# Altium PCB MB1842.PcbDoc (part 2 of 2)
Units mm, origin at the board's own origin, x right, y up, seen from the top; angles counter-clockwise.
Board outline 64.57 x 35 mm, 4 copper layers (Top Layer, MidLayer 1, MidLayer 2, Bottom Layer), stack 1.066 mm thick; 81 components, 72 nets, 272 pads, 1151 vias.
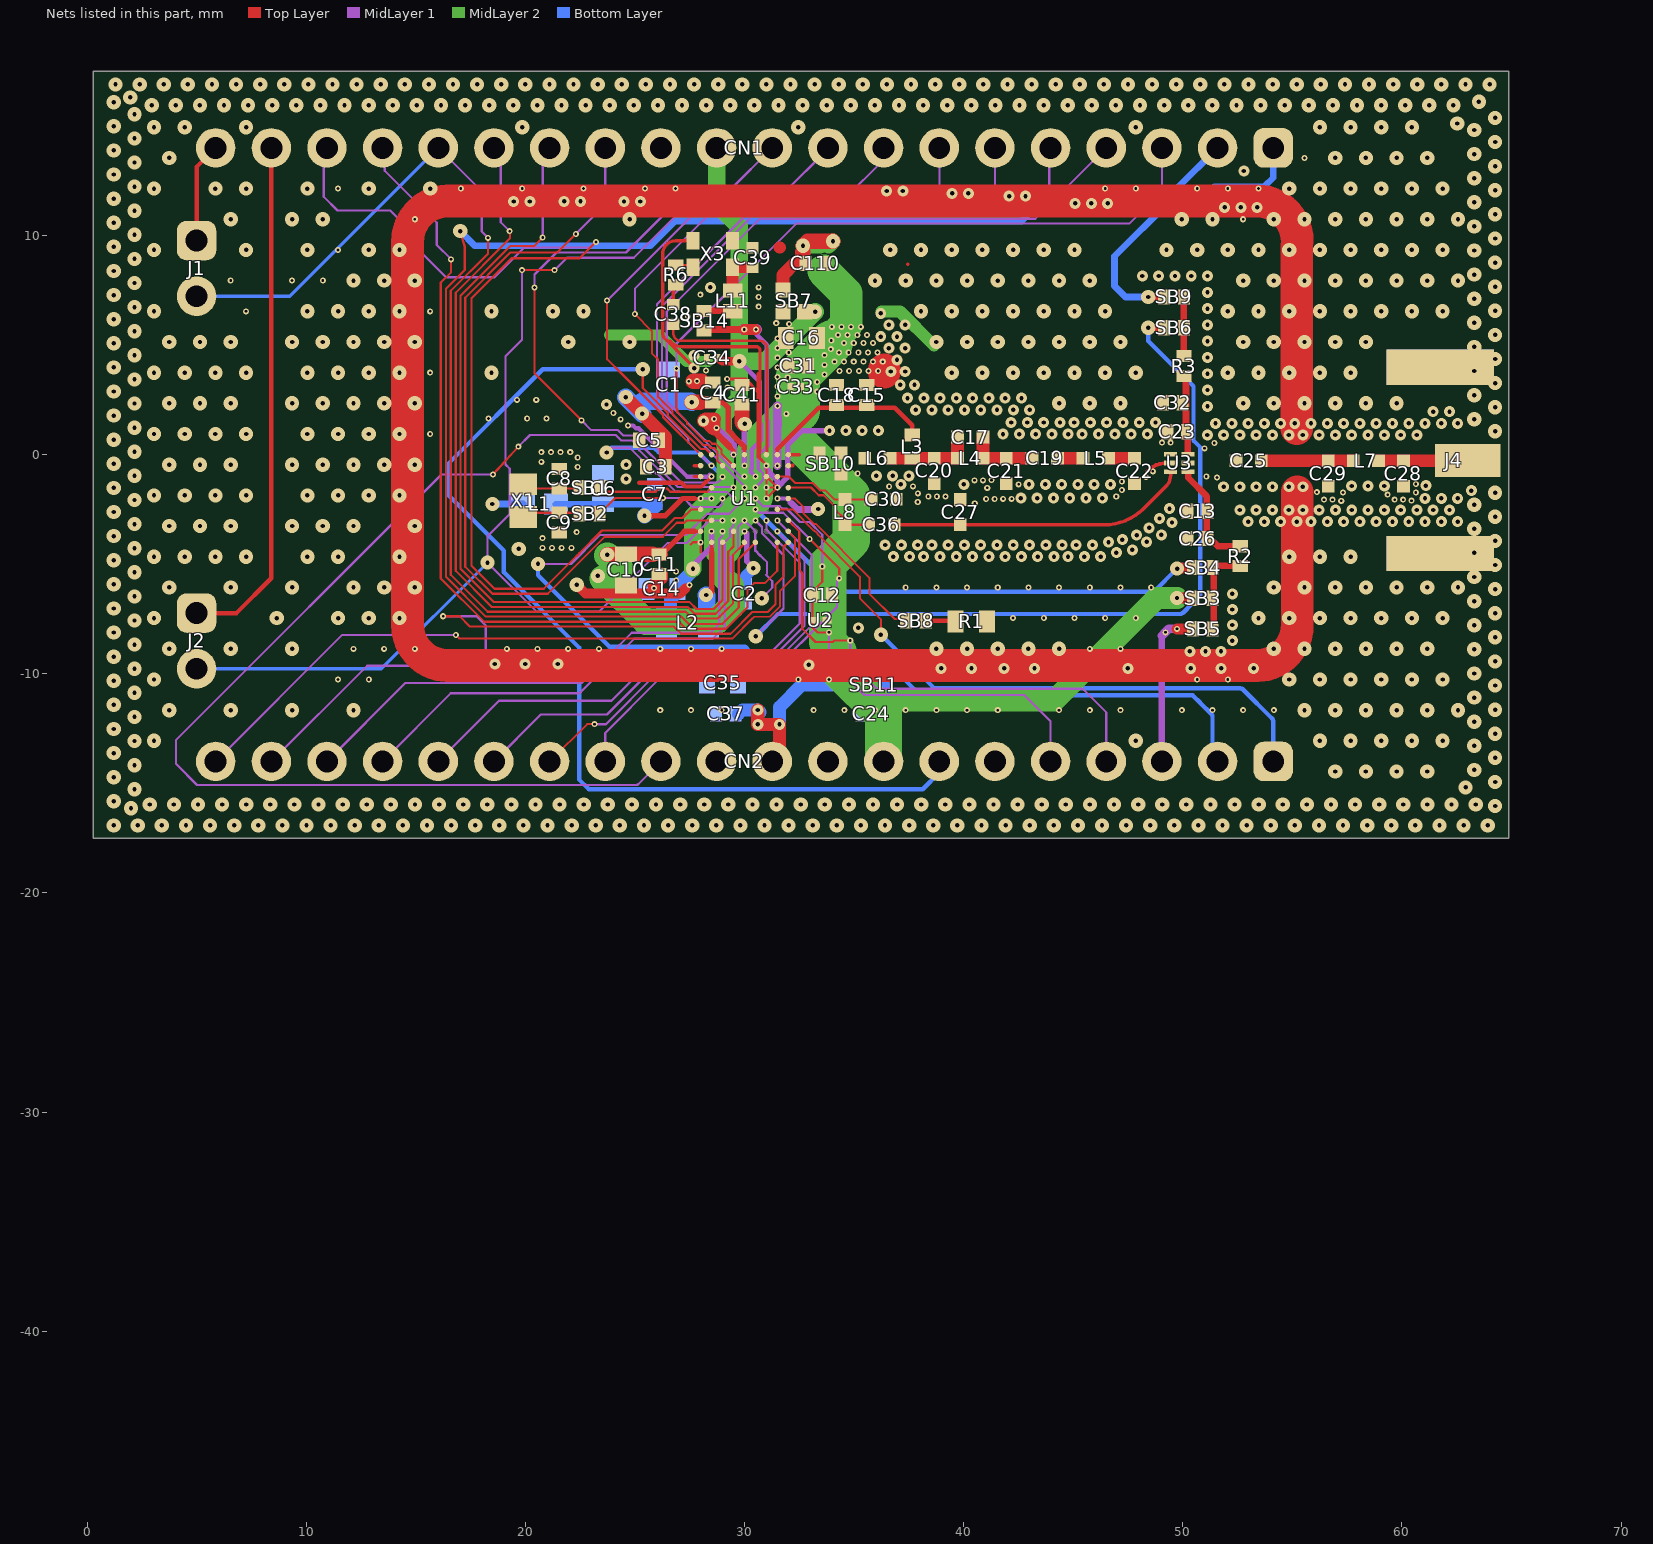
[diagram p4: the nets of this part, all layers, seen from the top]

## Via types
v1: diameter 0.65, hole 0.2, Top Layer to Bottom Layer, 646 vias
v2: diameter 0.275, hole 0.125, Top Layer to MidLayer 1, 261 vias
v3: diameter 0.5, hole 0.2, Top Layer to Bottom Layer, 244 vias

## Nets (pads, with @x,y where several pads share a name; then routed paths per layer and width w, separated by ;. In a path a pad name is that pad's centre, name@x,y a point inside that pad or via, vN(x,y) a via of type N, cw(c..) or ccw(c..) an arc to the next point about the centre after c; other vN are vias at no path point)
GND: C1.1 C2.1 C3.1 C4.1 C5.1 C6.2 C7.2 C8.2 C9.2 C10.2 C11.2 C12.2 C13.1 C14.2 C15.1 C16.2 C18.2 C20.2 C21.1 C22.1 C23.1 C24.2 C26.2 C27.1 C28.2 C29.2 C30.1 C31.2 C32.2 C33.1 C34.1 C35.2 C37.2 C39.1 C41.2 C110.2 CN1.12 CN2.6 CN2.9 CN2.11 J4.2 R1.1 U1.A1 U1.B7 U1.D9 U1.E3 U1.G5 U1.G6 U1.G7 U1.G8 U1.H6 U2.2 U3.2 X3.1 X3.2 | length 185.7
  Top Layer w0.1: 27.55,-4.1 27.65,-4 v2(28,-4) 28,-4.45 ; 28.26,-1.23 28.277,-1.23 ; 30.822,-0.285 31,-0.463 v2(31,-0.5) U1.G7@31,-1 ; U1.G7@31.008,-1 U1.G7@31,-1 ; v2(31,-1.5) v2(31,-2) v2(31.5,-1.5) ; v2(31,-1.5) v2(31.5,-1.5) ; v2(31,-1.5) U1.G7@31,-1 ; U1.G7@31,-1 v2(31.5,-1.5)
  Top Layer w0.15: 27.129,4.929 cw(c27.129,5.562) 26.626,5.177 ; v3@27.614,4.053 26.49,5.177 ; X3.2@27.649,9.76 26.867,9.76 ccw(c26.867,9.159) 26.533,9.658 ccw(c26.867,9.159) 26.368,9.493 ccw(c26.867,9.159) 26.266,9.159 26.266,5.536 ccw(c26.626,5.536) 26.321,5.346 26.435,5.232 ; 28.277,-1.23 28.5,-1.008 v2(28.5,-1) ; v2(29.214,3.454) 30.034,3.454 30.634,2.854 ; 30.529,4.929 cw(c30.529,4.748) 30.71,4.748 30.71,0.135 ccw(c31,0) 30.689,-0.075 cw(c30.634,-0.022) 30.634,-0.098 ; 30.634,3.698 30.634,2.854 ; 30.822,-0.285 30.634,-0.098 ; 37.446,8.695 37.448,8.697 ; 26.435,5.232 ccw(c26.626,5.536) 26.626,5.177 ; 26.435,5.232 26.49,5.177 ; 26.49,5.177 26.626,5.177 ; 30.634,-0.098 30.634,2.854
  Top Layer w0.16: 27.129,4.924 30.529,4.924 30.529,4.929
  Top Layer w0.17: 29.338,0.347 29.5,0.185 v2(29.5,0)
  Top Layer w0.18: 48.368,-0.759 cw(c49.284,-1.674) 49.284,-0.38 U3.2@49.448,-0.38
  Top Layer w0.2: 25.208,-1.275 27.12,-1.275 27.3,-1.455 28.035,-1.455 28.26,-1.23
  Top Layer w0.3: 28.753,0.932 29.338,0.347
  Top Layer w0.45: v1(22.349,-5.934) 22.749,-6.334 25.113,-6.334 27.072,-6.334 27.312,-6.094
  Top Layer w0.55: 31.606,9.448 31.613,9.454
  Top Layer w0.6: v2@25.865,-5.967 26.204,-5.628 C11.2@26.204,-5.452 ; v3@28.175,1.53 28.145,1.53 v3(28.132,1.544) 28.217,1.629 v2(28.621,1.629) 28.604,1.613 28.604,1.169 v3@28.212,1.561
  Top Layer w0.7: 27.67,3.355 27.708,3.355 v2(27.839,3.355) 28.058,3.355
  Top Layer w1.5: 36.377,3.769 36.377,3.865 ; 55.203,1.185 55.203,9.519 ; 55.225,-7.823 55.225,-1.707 ; 55.228,-7.775 cw(c53.378,-7.775) 53.378,-9.625 16.478,-9.625 cw(c16.478,-7.775) 14.628,-7.775 14.628,9.725 cw(c16.478,9.725) 16.478,11.575 53.378,11.575 cw(c53.378,9.725) 55.228,9.725
  MidLayer 1 w0.1: 29.5,-5.45 29.375,-5.325 29.375,-4.675 29.708,-4.342 29.708,-3.292 v2(30,-3) 30.442,-3.442 ; 30.718,-4.6 30.85,-4.733 31.034,-4.916 31.034,-5.434 30.982,-5.486 31.272,-5.776 31.272,-6.066 v1(30.788,-6.55)
  MidLayer 1 w0.12: 30.442,-3.442 30.5,-3.5 30.5,-4.382 30.718,-4.6
  MidLayer 1 w0.2: v2(24.691,1.329) 24.918,1.329 25.049,1.199 25.179,1.199 27.378,-1 v2(28.5,-1) v2@28.415,-0.915
  MidLayer 1 w0.25: v2(31,-0.5) 31,-0.631 31.109,-0.74 31.109,-0.796 31.5,-1.187 v2(31.5,-1.5) 31.974,-1.026 31.974,0.436 32.635,1.096 v3(33.881,1.096)
  MidLayer 1 w0.3: v2(28.73,1.223) 29.5,0.452 v2(29.5,0)
  MidLayer 2 w0.5: 23.838,5.458 26.144,5.458 27.358,4.244 28.362,4.244
  MidLayer 2 w0.55: v3@36.252,6.537 37.096,6.537 v1@38.64,4.993
  other v1: 1.215,-16.917 2.315,-16.917 3.415,-16.917 4.515,-16.917 5.615,-16.917 6.715,-16.917 7.815,-16.917 8.915,-16.917 10.015,-16.917 11.115,-16.917 12.215,-16.917 13.315,-16.917 14.415,-16.917 15.515,-16.917 16.615,-16.917 17.715,-16.917 18.815,-16.917 19.915,-16.917 21.015,-16.917 22.115,-16.917 23.215,-16.917 24.315,-16.917 25.415,-16.917 26.515,-16.917 27.615,-16.917 28.715,-16.917 29.815,-16.917 30.915,-16.917 32.015,-16.917 33.115,-16.917 34.215,-16.917 35.315,-16.917 36.415,-16.917 37.515,-16.917 38.615,-16.917 39.715,-16.917 40.815,-16.917 41.915,-16.917 43.015,-16.917 44.115,-16.917 45.215,-16.917 46.315,-16.917 47.415,-16.917 48.515,-16.917 49.615,-16.917 50.715,-16.917 51.815,-16.917 52.915,-16.917 54.015,-16.917 55.115,-16.917 56.215,-16.917 57.315,-16.917 58.415,-16.917 59.515,-16.917 60.615,-16.917 61.715,-16.917 62.815,-16.917 63.915,-16.917 2.005,-16.137 64.253,-16.034 2.865,-15.964 3.965,-15.964 5.065,-15.964 6.165,-15.964 7.265,-15.964 8.365,-15.964 9.465,-15.964 10.565,-15.964 11.665,-15.964 12.765,-15.964 13.865,-15.964 14.965,-15.964 16.065,-15.964 17.165,-15.964 18.265,-15.964 19.365,-15.964 20.465,-15.964 21.565,-15.964 22.665,-15.964 23.765,-15.964 24.865,-15.964 25.965,-15.964 27.065,-15.964 28.165,-15.964 29.265,-15.964 30.365,-15.964 31.465,-15.964 32.565,-15.964 33.665,-15.964 34.765,-15.964 35.865,-15.964 36.965,-15.964 38.065,-15.964 39.165,-15.964 40.265,-15.964 41.365,-15.964 42.465,-15.964 43.565,-15.964 44.665,-15.964 45.765,-15.964 46.865,-15.964 47.965,-15.964 49.065,-15.964 50.165,-15.964 51.265,-15.964 52.365,-15.964 53.465,-15.964 54.565,-15.964 55.665,-15.964 56.765,-15.964 57.865,-15.964 58.965,-15.964 60.065,-15.964 61.165,-15.964 62.265,-15.964 63.365,-15.964 1.215,-15.817 2.168,-15.267 62.908,-15.185 64.253,-14.934 1.215,-14.717 56.958,-14.458 58.358,-14.458 59.758,-14.458 61.158,-14.458 63.3,-14.384 2.168,-14.167 64.253,-13.834 1.215,-13.617 63.3,-13.284 2.168,-13.067 3.058,-13.058 47.858,-13.058 56.258,-13.058 57.658,-13.058 59.058,-13.058 60.458,-13.058 61.858,-13.058 64.253,-12.734 1.215,-12.517 63.3,-12.184 2.168,-11.967 3.758,-11.658 6.558,-11.658 9.358,-11.658 12.158,-11.658 55.558,-11.658 56.958,-11.658 58.358,-11.658 59.758,-11.658 61.158,-11.658 62.558,-11.658 64.253,-11.634 1.215,-11.417 63.3,-11.084 2.168,-10.867 64.253,-10.534 1.215,-10.317 3.058,-10.258 54.858,-10.258 56.258,-10.258 57.658,-10.258 59.058,-10.258 60.458,-10.258 61.858,-10.258 63.3,-9.984 2.168,-9.767 64.253,-9.434 1.215,-9.217 63.3,-8.884 3.758,-8.858 6.558,-8.858 9.358,-8.858 38.758,-8.858 40.158,-8.858 41.558,-8.858 42.958,-8.858 44.358,-8.858 54.158,-8.858 55.558,-8.858 56.958,-8.858 58.358,-8.858 59.758,-8.858 61.158,-8.858 2.168,-8.667 64.253,-8.334 1.215,-8.117 63.3,-7.784 2.168,-7.567 3.058,-7.458 8.658,-7.458 11.458,-7.458 12.858,-7.458 14.258,-7.458 53.458,-7.458 54.858,-7.458 56.258,-7.458 57.658,-7.458 59.058,-7.458 60.458,-7.458 61.858,-7.458 64.253,-7.234 1.215,-7.017 63.3,-6.684 2.168,-6.467 64.253,-6.134 3.758,-6.058 6.558,-6.058 9.358,-6.058 12.158,-6.058 13.558,-6.058 14.958,-6.058 54.158,-6.058 55.558,-6.058 56.958,-6.058 58.358,-6.058 59.758,-6.058 61.158,-6.058 62.558,-6.058 1.215,-5.917 63.3,-5.584 2.168,-5.367 64.253,-5.034 1.215,-4.817 3.058,-4.658 4.458,-4.658 5.858,-4.658 7.258,-4.658 10.058,-4.658 11.458,-4.658 14.258,-4.658 54.858,-4.658 56.258,-4.658 57.658,-4.658 63.3,-4.484 19.7,-4.3 2.168,-4.267 64.253,-3.934 1.215,-3.717 63.3,-3.384 3.758,-3.258 5.158,-3.258 6.558,-3.258 9.358,-3.258 10.758,-3.258 12.158,-3.258 14.958,-3.258 2.168,-3.167 64.253,-2.834 1.215,-2.617 63.3,-2.284 2.168,-2.067 3.058,-1.858 4.458,-1.858 5.858,-1.858 7.258,-1.858 10.058,-1.858 11.458,-1.858 12.858,-1.858 14.258,-1.858 64.253,-1.734 1.215,-1.517 2.168,-0.967 3.758,-0.458 5.158,-0.458 6.558,-0.458 9.358,-0.458 10.758,-0.458 12.158,-0.458 13.558,-0.458 14.958,-0.458 1.215,-0.417 2.168,0.133 1.215,0.683 3.058,0.942 4.458,0.942 5.858,0.942 7.258,0.942 10.058,0.942 11.458,0.942 12.858,0.942 14.258,0.942 64.253,1.066 2.168,1.233 63.3,1.616 1.215,1.783 64.253,2.166 2.168,2.333 3.758,2.342 5.158,2.342 6.558,2.342 9.358,2.342 10.758,2.342 12.158,2.342 13.558,2.342 14.958,2.342 44.358,2.342 45.758,2.342 47.158,2.342 52.758,2.342 54.158,2.342 55.558,2.342 56.958,2.342 58.358,2.342 59.758,2.342 63.3,2.716 1.215,2.883 64.253,3.266 2.168,3.433 3.058,3.742 4.458,3.742 5.858,3.742 7.258,3.742 10.058,3.742 11.458,3.742 12.858,3.742 14.258,3.742 18.458,3.742 39.458,3.742 40.858,3.742 42.258,3.742 43.658,3.742 45.058,3.742 46.458,3.742 47.858,3.742 52.058,3.742 53.458,3.742 54.858,3.742 56.258,3.742 57.658,3.742 63.3,3.816 1.215,3.983 64.253,4.366 2.168,4.533 63.3,4.916 1.215,5.083 3.758,5.142 5.158,5.142 6.558,5.142 9.358,5.142 10.758,5.142 12.158,5.142 13.558,5.142 14.958,5.142 21.958,5.142 24.758,5.142 38.758,5.142 40.158,5.142 41.558,5.142 42.958,5.142 44.358,5.142 45.758,5.142 47.158,5.142 52.758,5.142 54.158,5.142 55.558,5.142 56.958,5.142 58.358,5.142 64.253,5.466 2.168,5.633 63.3,6.016 1.215,6.183 3.058,6.542 10.058,6.542 11.458,6.542 12.858,6.542 14.258,6.542 18.458,6.542 21.258,6.542 22.658,6.542 38.058,6.542 39.458,6.542 40.858,6.542 42.258,6.542 43.658,6.542 45.058,6.542 46.458,6.542 52.058,6.542 53.458,6.542 54.858,6.542 56.258,6.542 57.658,6.542 59.058,6.542 60.458,6.542 61.858,6.542 64.253,6.566 2.168,6.733 63.3,7.116 1.215,7.283 64.253,7.666 2.168,7.833 12.158,7.942 13.558,7.942 14.958,7.942 35.958,7.942 37.358,7.942 38.758,7.942 40.158,7.942 41.558,7.942 42.958,7.942 44.358,7.942 45.758,7.942 52.758,7.942 54.158,7.942 55.558,7.942 56.958,7.942 58.358,7.942 59.758,7.942 61.158,7.942 62.558,7.942 63.3,8.216 1.215,8.383 64.253,8.766 2.168,8.933 63.3,9.316 3.058,9.342 7.258,9.342 10.058,9.342 12.858,9.342 14.258,9.342 36.658,9.342 38.058,9.342 39.458,9.342 40.858,9.342 42.258,9.342 43.658,9.342 45.058,9.342 49.258,9.342 50.658,9.342 52.058,9.342 53.458,9.342 54.858,9.342 56.258,9.342 57.658,9.342 59.058,9.342 60.458,9.342 61.858,9.342 1.215,9.483 64.253,9.866 2.168,10.033 63.3,10.416 1.215,10.583 6.558,10.742 9.358,10.742 10.758,10.742 24.758,10.742 49.958,10.742 51.358,10.742 54.158,10.742 55.558,10.742 56.958,10.742 58.358,10.742 59.758,10.742 61.158,10.742 62.558,10.742 64.253,10.966 2.168,11.133 63.3,11.516 1.215,11.683 64.253,12.066 3.058,12.142 5.858,12.142 7.258,12.142 10.058,12.142 12.858,12.142 15.658,12.142 54.858,12.142 56.258,12.142 57.658,12.142 59.058,12.142 60.458,12.142 61.858,12.142 2.168,12.233 63.3,12.616 1.215,12.783 64.253,13.166 2.168,13.333 3.758,13.542 56.958,13.542 58.358,13.542 59.758,13.542 61.158,13.542 63.3,13.716 1.215,13.883 64.253,14.266 2.168,14.433 63.3,14.816 3.058,14.942 4.458,14.942 7.258,14.942 19.858,14.942 32.458,14.942 47.858,14.942 56.258,14.942 57.658,14.942 59.058,14.942 60.458,14.942 1.215,14.983 62.526,15.112 64.253,15.366 2.168,15.533 2.952,15.942 4.052,15.942 5.152,15.942 6.252,15.942 7.352,15.942 8.452,15.942 9.552,15.942 10.652,15.942 11.752,15.942 12.852,15.942 13.952,15.942 15.052,15.942 16.152,15.942 17.252,15.942 18.352,15.942 19.452,15.942 20.552,15.942 21.652,15.942 22.752,15.942 23.852,15.942 24.952,15.942 26.052,15.942 27.152,15.942 28.252,15.942 29.352,15.942 30.452,15.942 31.552,15.942 32.652,15.942 33.752,15.942 34.852,15.942 35.952,15.942 37.052,15.942 38.152,15.942 39.252,15.942 40.352,15.942 41.452,15.942 42.552,15.942 43.652,15.942 44.752,15.942 45.852,15.942 46.952,15.942 48.052,15.942 49.152,15.942 50.252,15.942 51.352,15.942 52.452,15.942 53.552,15.942 54.652,15.942 55.752,15.942 56.852,15.942 57.952,15.942 59.052,15.942 60.152,15.942 61.252,15.942 62.352,15.942 1.215,16.083 63.513,16.099 1.97,16.301 1.302,16.895 2.402,16.895 3.502,16.895 4.602,16.895 5.702,16.895 6.802,16.895 7.902,16.895 9.002,16.895 10.102,16.895 11.202,16.895 12.302,16.895 13.402,16.895 14.502,16.895 15.602,16.895 16.702,16.895 17.802,16.895 18.902,16.895 20.002,16.895 21.102,16.895 22.202,16.895 23.302,16.895 24.402,16.895 25.502,16.895 26.602,16.895 27.702,16.895 28.802,16.895 29.902,16.895 31.002,16.895 32.102,16.895 33.202,16.895 34.302,16.895 35.402,16.895 36.502,16.895 37.602,16.895 38.702,16.895 39.802,16.895 40.902,16.895 42.002,16.895 43.102,16.895 44.202,16.895 45.302,16.895 46.402,16.895 47.502,16.895 48.602,16.895 49.702,16.895 50.802,16.895 51.902,16.895 53.002,16.895 54.102,16.895 55.202,16.895 56.302,16.895 57.402,16.895 58.502,16.895 59.602,16.895 60.702,16.895 61.802,16.895 62.902,16.895 64.002,16.895
  other v2: 26.158,-11.658 27.558,-11.658 28.958,-11.658 33.158,-11.658 34.558,-11.658 35.958,-11.658 37.358,-11.658 38.758,-11.658 40.158,-11.658 41.558,-11.658 44.358,-11.658 45.758,-11.658 47.158,-11.658 49.958,-11.658 51.358,-11.658 52.758,-11.658 54.158,-11.658 11.458,-10.258 12.858,-10.258 32.458,-10.258 33.858,-10.258 50.658,-10.258 52.058,-10.258 12.158,-8.858 13.558,-8.858 14.958,-8.858 19.158,-8.858 20.558,-8.858 21.958,-8.858 23.358,-8.858 26.158,-8.858 27.558,-8.858 28.958,-8.858 45.758,-8.858 47.158,-8.858 42.258,-7.458 43.658,-7.458 45.058,-7.458 46.458,-7.458 47.858,-7.458 25.868,-6.09 37.358,-6.058 38.758,-6.058 40.158,-6.058 41.558,-6.058 42.958,-6.058 44.358,-6.058 45.758,-6.058 47.158,-6.058 48.558,-6.058 27.495,-5.952 26.885,-5.738 26.885,-5.33 20.78,-4.252 21.221,-4.252 21.662,-4.252 22.103,-4.252 20.78,-3.811 22.343,-3.539 40.509,-2.219 37.908,-2.157 57.233,-2.109 60.44,-2.101 56.449,-2.054 56.838,-2.056 59.669,-2.053 60.058,-2.055 41.029,-2.019 41.418,-2.018 41.807,-2.016 42.196,-2.015 38.391,-1.909 38.78,-1.911 39.169,-1.912 46.965,-1.913 59.352,-1.829 37.91,-1.765 56.119,-1.713 57.314,-1.729 60.634,-1.728 47.218,-1.615 41.08,-1.511 36.606,-1.454 37.686,-1.444 42.514,-1.351 60.636,-1.339 47.22,-1.223 40.497,-1.17 40.886,-1.168 41.275,-1.167 51.56,-1.047 48.334,-1.012 51.077,-0.998 35.167,-0.859 48.635,-0.762 22.388,-0.568 20.728,-0.326 22.388,-0.127 20.728,0.115 21.169,0.115 21.61,0.115 22.051,0.115 50.998,0.289 49.05,0.549 49.449,0.549 51.441,0.533 15.658,0.942 24.353,1.613 18.322,1.648 20.086,1.648 20.967,1.648 24.015,1.896 19.617,2.501 20.499,2.501 33.317,2.874 29.224,3.075 33.317,3.315 27.459,3.346 33.655,3.66 15.658,3.742 34.34,3.814 34.781,3.814 35.222,3.814 35.663,3.814 36.103,3.814 28.244,3.84 33.655,4.101 34.106,4.241 34.547,4.241 34.988,4.241 35.429,4.241 35.869,4.241 36.31,4.241 33.655,4.542 34.313,4.667 34.754,4.667 35.194,4.667 35.635,4.667 36.076,4.667 33.942,4.813 34.547,5.093 34.988,5.093 35.428,5.093 35.869,5.093 33.966,5.21 34.266,5.464 34.707,5.464 35.148,5.464 35.589,5.464 33.986,5.835 34.426,5.835 34.867,5.835 35.308,5.835 27.418,6.313 7.258,6.542 15.658,6.542 30.649,6.755 30.649,7.196 27.987,7.3 30.649,7.637 6.558,7.942 9.358,7.942 10.758,7.942 11.458,9.342 14.958,10.742 52.758,10.742 11.458,12.142 17.058,12.142 19.858,12.142 22.658,12.142 25.458,12.142 26.858,12.142 46.458,12.142 47.858,12.142 50.658,12.142 52.058,12.142 53.458,12.142 55.558,13.542
  other v3: 38.976,-9.752 40.363,-9.752 41.849,-9.752 43.235,-9.752 47.494,-9.752 50.366,-9.752 51.753,-9.752 53.239,-9.752 32.938,-9.592 18.609,-9.554 19.996,-9.554 21.482,-9.554 50.327,-8.977 51.037,-8.977 51.747,-8.977 52.265,-8.484 35.2,-7.9 52.265,-7.774 52.265,-7.064 52.265,-6.354 36.792,-4.654 37.535,-4.654 38.178,-4.654 38.922,-4.654 39.665,-4.654 40.408,-4.654 41.151,-4.654 41.894,-4.654 42.637,-4.654 43.38,-4.654 44.123,-4.654 44.767,-4.654 45.51,-4.654 46.253,-4.654 46.973,-4.469 47.705,-4.34 36.42,-4.122 37.163,-4.122 37.907,-4.122 38.55,-4.122 39.293,-4.122 40.036,-4.122 40.779,-4.122 41.522,-4.122 42.265,-4.122 43.008,-4.122 43.752,-4.122 44.495,-4.122 45.138,-4.122 45.881,-4.122 46.613,-3.993 48.352,-3.976 47.246,-3.882 47.896,-3.671 49.026,-3.662 48.464,-3.337 49.51,-3.098 52.982,-3.058 53.725,-3.058 54.468,-3.058 55.211,-3.058 55.854,-3.058 56.597,-3.058 57.34,-3.058 58.083,-3.058 58.827,-3.058 59.57,-3.058 60.313,-3.058 61.056,-3.058 61.799,-3.058 62.542,-3.058 48.942,-2.914 52.61,-2.527 53.353,-2.527 54.096,-2.527 54.839,-2.527 55.482,-2.527 56.225,-2.527 56.968,-2.527 57.712,-2.527 58.455,-2.527 59.198,-2.527 59.941,-2.527 60.684,-2.527 61.427,-2.527 62.17,-2.527 49.397,-2.46 42.614,-1.988 43.357,-1.988 44.1,-1.988 44.844,-1.988 45.587,-1.988 46.33,-1.988 61.055,-1.995 61.798,-1.995 62.541,-1.995 63.17,-1.64 51.866,-1.464 52.609,-1.464 53.352,-1.464 54.095,-1.464 54.838,-1.464 55.481,-1.464 57.71,-1.429 58.453,-1.429 59.197,-1.429 61.09,-1.411 37.14,-1.356 40.013,-1.356 42.985,-1.356 43.729,-1.356 44.472,-1.356 45.215,-1.356 45.958,-1.356 46.701,-1.356 24.598,-1.104 36.019,-0.967 36.762,-0.967 37.505,-0.967 24.598,-0.458 51.123,0.898 51.866,0.898 52.609,0.898 53.352,0.898 54.095,0.898 54.838,0.898 55.481,0.898 56.225,0.898 56.968,0.898 57.711,0.898 58.454,0.898 59.197,0.898 59.94,0.898 60.683,0.898 41.798,0.938 42.541,0.938 43.284,0.938 44.027,0.938 44.77,0.938 45.413,0.938 46.156,0.938 46.899,0.938 47.643,0.938 48.386,0.938 34.624,1.096 35.367,1.096 36.11,1.096 51.495,1.43 52.238,1.43 52.981,1.43 53.724,1.43 54.467,1.43 55.11,1.43 55.853,1.43 56.596,1.43 57.34,1.43 58.083,1.43 58.826,1.43 59.569,1.43 60.312,1.43 61.055,1.43 61.798,1.43 62.541,1.43 42.169,1.469 42.913,1.469 43.656,1.469 44.399,1.469 45.042,1.469 45.785,1.469 46.528,1.469 47.271,1.469 48.014,1.469 48.758,1.469 61.427,1.961 62.17,1.961 37.812,2.046 38.555,2.046 39.297,2.046 40.04,2.046 40.784,2.046 41.527,2.046 42.27,2.046 43.013,2.046 51.132,2.205 23.706,2.287 37.441,2.577 38.184,2.577 38.927,2.577 39.669,2.577 40.412,2.577 41.155,2.577 41.898,2.577 42.641,2.577 51.132,2.948 37.109,3.185 37.758,3.186 51.132,3.692 36.683,3.794 37.332,3.794 27.708,3.949 36.961,4.326 51.132,4.435 27.708,4.532 36.59,4.857 37.333,4.857 51.132,5.178 36.219,5.389 36.962,5.389 36.591,5.92 37.334,5.92 51.132,5.921 36.219,6.452 51.132,6.664 51.132,7.407 28.441,7.636 48.16,8.15 48.903,8.15 49.646,8.15 50.389,8.15 51.132,8.15 51.912,11.286 52.655,11.286 53.399,11.286 45.088,11.465 45.832,11.465 46.575,11.465 19.467,11.55 20.21,11.55 24.503,11.554 25.246,11.554 21.776,11.558 22.519,11.558 42.082,11.793 42.825,11.793 39.477,11.926 40.22,11.926 36.488,12.029 37.231,12.029 52.785,12.942
NetC6_1: C6.1 C7.1 L1.2 U1.A5 U1.B5 | length 8.2
  Top Layer w0.15: 27.7,-2 v2(28,-2)
  Top Layer w0.25: v1@25.623,-2.796 26.378,-2.796 27.174,-2 27.7,-2
  MidLayer 1 w0.1: v2(28,-2) v2(28.5,-2)
  Bottom Layer w0.25: C6.1@23.45,-2.462 C6.1@23.462,-2.45
  Bottom Layer w0.3: L1.2@21.4,-2.262 C6.1@23.55,-2.262 ; C6.1@23.678,-2.266 23.688,-2.256 C7.1@25.89,-2.256
  Bottom Layer w0.7: v1(25.441,-2.788) C7.1@25.9,-2.33
NetC8_1: C8.1 SB1.2 X1.2 | length 2.8
  Top Layer w0.1: X1.2@19.9,-1.75 X1.2@19.95,-1.8 ; X1.2@19.9,-1.35 20.1,-1.55 C8.1@21.55,-1.55 22.431,-1.55 SB1.2@22.481,-1.5
NetC9_1: C9.1 SB2.2 X1.1 | length 3
  Top Layer w0.1: X1.1@19.9,-3.25 X1.1@20.15,-3 ; X1.1@19.9,-2.85 20.1,-2.65 C9.1@21.55,-2.65 22.431,-2.65 SB2.2@22.481,-2.7
NetC12_1: C12.1 CN2.5 U1.F5 U2.1 | length 23.3
  Top Layer w0.1: U2.1@33.1,-7.513 C12.1@33.1,-6.407 33.1,-6.251 33.55,-5.801 v2(33.55,-5.1) ; U2.1@33.144,-7.557 33.144,-7.92 33.331,-8.108 v2(33.853,-8.108)
  MidLayer 1 w0.1: v2(30.5,-2) 30.85,-2.35 31.612,-2.35 31.722,-2.46 31.923,-2.46 32.537,-3.074 32.969,-3.074 33.55,-3.655 v2(33.55,-5.1) ; v2(33.853,-8.108) 33.853,-9.338 35.481,-10.966 42.767,-10.966 43.97,-12.169 CN2.5@43.97,-14
NetC13_2: C13.2 C26.1 R2.1 U3.4 | length 5.3
  Top Layer w0.15: U3.4@50.231,-0.797 U3.4@50.248,-0.78
  Top Layer w0.3: 50.248,-0.892 50.248,-1.056 51.103,-1.912 51.103,-3.675 51.606,-4.178 R2.1@52.543,-4.178 ; R2.1@52.418,-4.156 ccw(c52.618,-3.278) R2.1@52.539,-4.175 ; R2.1@52.418,-4.053 R2.1@52.539,-4.175 ; R2.1@52.539,-4.175 ccw(c52.618,-3.278) R2.1@52.618,-4.178 R2.1@52.543,-4.178 ; R2.1@52.539,-4.175 R2.1@52.543,-4.178
NetC15_2: C15.2 C18.1 L3.2 U1.H9 | length 8
  Top Layer w0.15: U1.H9@31.5,0 31.5,0.248
  Top Layer w0.2: 31.5,0.248 33.394,2.142 33.47,2.142 C18.1@34.204,2.142 ; C18.1@34.204,2.144 36.854,2.144 37.66,1.338 L3.2@37.66,0.897
NetC17_1: C17.1 C20.1 L3.1 L4.1 L6.1 | length 3.8
  Top Layer w0.582: L6.1@36.645,-0.163 L3.1@37.66,-0.163 C20.1@38.658,-0.163 39.519,-0.163 L4.1@39.52,-0.164 ; L4.1@39.72,-0.164 C17.1@39.72,0.801
NetC17_2: C17.2 C19.2 C21.2 L4.2 | length 3
  Top Layer w0.582: C17.2@40.88,0.801 L4.2@40.88,-0.164 41.548,-0.164 41.551,-0.167 C21.2@41.951,-0.167 42.924,-0.167 C19.2@42.927,-0.164
NetC19_1: C19.1 L5.1 | length 1
  Top Layer w0.582: C19.1@44.287,-0.164 L5.1@45.251,-0.164
NetC22_2: C22.2 L5.2 U3.1 | length 1.2
  Top Layer w0.582: L5.2@46.611,-0.167 C22.2@47.8,-0.167
NetC23_2: C23.2 C32.1 R3.1 U3.6 | length 3.4
  Top Layer w0.3: R3.1@50.056,3.594 50.144,3.506 50.144,3.161 50.147,3.157 C23.2@50.147,1.044 ; C23.2@50.198,1.044 C23.2@50.221,1.02 ; U3.6@50.225,0.082 C23.2@50.225,0.834
NetC25_1: C25.1 U3.5
NetC25_2: C25.2 C29.1 L7.1 | length 4.2
  Top Layer w0.582: C25.2@53.586,-0.283 56.744,-0.283 L7.1@57.777,-0.283
NetC27_2: C27.2 C36.2 U3.3 | length 13.7
  Top Layer w0.161: C36.2@36.83,-3.2 36.832,-3.202 C27.2@39.849,-3.202 46.42,-3.202 ccw(c46.42,-0.662) 48.216,-2.458 49.256,-1.417 ccw(c48.794,-0.955) 49.448,-0.955 U3.3@49.448,-0.78
NetC28_1: C28.1 J4.1 L7.2 | length 2.8
  Top Layer w0.582: L7.2@58.937,-0.283 59.969,-0.283 61.749,-0.283 J4.1@61.77,-0.261
NetC38_1: C38.1 R6.2 | length 1
  Top Layer w0.15: C38.1@26.751,6.849 26.751,7.754 R6.2@26.866,7.754
NetC39_2: C39.2 L11.1 X3.4 | length 2
  Top Layer w0.5: X3.4@29.449,8.56 29.456,8.553 29.462,8.546 30.364,8.546 C39.2@30.369,8.541
  Top Layer w0.55: X3.4@29.456,8.553 29.456,7.501 L11.1@29.463,7.494
NetCN1_1: CN1.1 SB9.1 | length 13.9
  Top Layer w0.3: v1(48.427,7.195) SB9.1@49.15,7.195
  Bottom Layer w0.3: v1(48.427,7.195) 47.389,7.195 46.887,7.697 46.887,9.052 49.37,11.535 50.77,11.535 51.467,12.232 53.722,12.232 54.13,12.64 CN1.1@54.13,14
NetCN1_2: CN1.2 U1.F1 | length 70.7
  Top Layer w0.1: v1(17.028,10.201) 17.234,9.492 17.234,8.424 16.382,7.571 16.382,-5.574 18.197,-7.389 27.125,-7.389 27.463,-7.728 28.991,-7.728 29.743,-6.976 29.743,-4.757 U1.F1@30.5,-4
  Bottom Layer w0.3: v1(17.028,10.201) 17.704,9.524 25.7,9.524 26.84,10.664 42.651,10.664 44.128,12.14 49.73,12.14 CN1.2@51.59,14
NetCN1_3: CN1.3 U1.D8 | length 33.9
  Top Layer w0.1: v2(26.895,3.933) 26.887,3.925 26.887,2.123 26.931,2.079 26.931,1.938 27.385,1.484 27.385,1.409 28.164,0.63 28.393,0.63 28.527,0.497 28.687,0.497 28.954,0.23 28.954,0.046 U1.D8@29.5,-0.5
  MidLayer 1 w0.1: v2(26.895,3.933) 26.895,5.073 32.364,10.542 47.566,10.542 49.05,12.026 CN1.3@49.05,14
NetCN1_4: CN1.4 U1.E7 | length 32.2
  MidLayer 1 w0.1: v2(30,-1) 29.834,-1 28.217,0.617 28.217,0.66 26.455,2.422 26.455,6.521 30.696,10.762 43.272,10.762 CN1.4@46.51,14
NetCN1_5: CN1.5 U1.E6 | length 31.7
  MidLayer 1 w0.1: v2(30,-1.5) 30,-1.434 26.419,2.147 26.235,2.331 26.235,6.771 29.901,10.437 30.452,10.988 38.058,10.988 38.06,10.99 42.963,10.99 43.907,11.934 43.907,13.937 CN1.5@43.97,14
NetCN1_6: CN1.6 U1.B8 | length 27.8
  MidLayer 1 w0.1: v2(28.5,-0.5) 27.431,0.569 27.431,0.75 26.015,2.166 26.015,6.876 30.347,11.208 37.967,11.208 37.969,11.21 40.426,11.21 41.43,12.214 CN1.6@41.43,14
NetCN1_7: CN1.7 U1.C8 | length 27.6
  Top Layer w0.09: v2(24.998,6.424) 25.78,5.642 25.78,4.63 26.055,4.355 26.055,2.651 26.716,1.99 26.716,1.849 27.17,1.395 27.17,1.362 28.088,0.445 28.317,0.445 28.45,0.312 28.611,0.312 28.769,0.153 28.769,-0.269 U1.C8@29,-0.5
  MidLayer 1 w0.09: v2(24.998,6.424) 24.998,7.576 28.845,11.423 37.878,11.423 37.88,11.425 38.114,11.425 38.89,12.201 CN1.7@38.89,14
NetCN1_8: CN1.8 U1.A9 | length 24.6
  Top Layer w0.1: v2(23.733,7.031) 23.733,4.358 24.387,3.705 26.281,1.81 26.281,1.719 U1.A9@28,0
  MidLayer 1 w0.1: v2(23.733,7.031) 28.359,11.657 29.55,11.657 29.553,11.661 34.547,11.661 36.35,13.464 CN1.8@36.35,14
NetCN1_9: CN1.9 J2.2 U1.C3 | length 59.1
  Top Layer w0.1: v2(19.85,8.42) v2(21.331,8.42)
  MidLayer 1 w0.1: v2(19.85,8.42) 19.85,5.25 19.096,4.496 19.096,-0.449 19.291,-0.644 19.291,-2.707 18.275,-3.724 v1(18.275,-4.925) 20.519,-7.169 23.36,-7.169 26.504,-4.025 27.375,-4.025 28.4,-3 v2(29,-3) ; v2(21.331,8.42) 21.9,8.989 24.955,8.989 27.844,11.877 29.459,11.877 29.462,11.881 31.74,11.881 33.81,13.951 CN1.9@33.81,14
  Bottom Layer w0.15: J2.2@5,-9.77 13.43,-9.77 v1(18.275,-4.925)
NetCN1_10: CN1.10 U1.C7 | length 28.6
  Top Layer w0.1: v2(20.418,7.624) 20.418,3.718 v2(22.567,1.569) ; U1.C7@28.987,-1.013 28.993,-1.013 v2(28.997,-1.009) U1.C7@29,-1.006
  MidLayer 1 w0.09: v2@28.997,-1.054 v2(28.997,-1.009)
  MidLayer 1 w0.1: v2(20.418,7.624) 20.418,8.22 21.423,9.225 24.596,9.225 27.468,12.097 29.367,12.097 CN1.10@31.27,14 ; v2(22.567,1.569) 23.016,1.12 24.228,1.12 24.477,0.87 24.852,0.87 24.969,0.87 25.42,0.419 25.42,0.302 26.142,-0.42 26.27,-0.42 27.125,-1.275 28.383,-1.275 28.385,-1.278 28.615,-1.278 28.617,-1.275 28.776,-1.275 v2@28.997,-1.054
NetCN1_13: CN1.13 U1.B3 | length 36.2
  Top Layer w0.1: v2(22.303,10.066) 21.462,9.225 19.32,9.225 17.262,7.167 17.262,-5.112 18.5,-6.35 21.023,-6.35 23.629,-3.744 26.279,-3.744 26.912,-3.111 27.266,-3.111 27.377,-3 U1.B3@28.5,-3
  MidLayer 1 w0.1: v2(22.303,10.066) 23.65,11.413 CN1.13@23.65,14
NetCN1_14: CN1.14 U1.C1 | length 37.2
  Top Layer w0.1: v2@20.79,9.905 20.409,9.524 19.308,9.524 17.042,7.258 17.042,-5.203 18.568,-6.729 27.499,-6.729 27.809,-7.039 28.593,-7.039 29,-6.632 U1.C1@29,-4
  MidLayer 1 w0.1: v2(20.792,9.908) 20.792,13.682 CN1.14@21.11,14 CN1.14@21.11,13.835
NetCN1_15: CN1.15 U1.D2 | length 37.4
  Top Layer w0.1: v2@19.297,10.164 19.297,9.864 16.822,7.389 16.822,-5.303 18.468,-6.949 27.408,-6.949 27.718,-7.259 28.684,-7.259 29.264,-6.68 29.264,-4.431 29.5,-4.195 U1.D2@29.5,-3.5
  MidLayer 1 w0.1: CN1.15@18.57,14 18.877,13.693 18.877,10.609 v2(19.289,10.197)
NetCN1_16: CN1.16 J1.2 U1.E1 | length 52.1
  Top Layer w0.1: CN1.16@15.909,13.879 CN1.16@16.03,14 ; v2(18.295,9.897) 18.295,9.173 16.602,7.48 16.602,-5.483 18.288,-7.169 27.317,-7.169 27.627,-7.479 28.775,-7.479 29.158,-7.096 29.162,-7.096 29.484,-6.775 29.484,-4.566 U1.E1@30,-4.05
  MidLayer 1 w0.1: CN1.16@16.03,14 18.011,12.019 18.011,10.181 v2(18.295,9.897)
  Bottom Layer w0.15: J1.2@5,7.23 9.26,7.23 CN1.16@16.03,14
NetCN1_17: CN1.17 U1.H1 | length 40.3
  Top Layer w0.1: v2@16.616,8.911 16.616,8.33 16.144,7.859 16.144,-5.648 18.123,-7.626 27.012,-7.626 27.334,-7.948 29.157,-7.948 30.14,-6.965 30.14,-6.165 30.444,-5.861 30.933,-5.861 31.5,-5.294 U1.H1@31.5,-4
  MidLayer 1 w0.1: CN1.17@13.49,14 13.49,13.287 13.59,13.187 13.59,12.954 15.959,10.584 15.959,9.568 v2(16.614,8.914)
NetCN1_18: CN1.18 U1.A4 | length 48.5
  Top Layer w0.1: v2(23.221,9.708) 22.475,8.962 19.368,8.962 17.541,7.134 17.541,-5.067 17.778,-5.305 ccw(c18.275,-4.925) 17.895,-5.422 18.596,-6.122 20.84,-6.122 22.35,-4.613 ccw(c22.103,-4.252) 22.464,-4.498 23.504,-3.459 26.252,-3.459 26.82,-2.891 27.175,-2.891 27.565,-2.5 U1.A4@28,-2.5
  MidLayer 1 w0.1: CN1.18@10.95,14 10.805,13.855 10.805,11.771 11.431,11.146 13.837,11.146 14.986,9.997 14.986,9.489 16.38,8.095 18.596,8.095 19.955,9.453 22.966,9.453 v2(23.221,9.708) v2@23.222,9.706
NetCN1_19: CN1.19 J2.1 | length 23.7
  Top Layer w0.2: J2.1@5,-7.23 6.822,-7.23 8.41,-5.642 CN1.19@8.41,14
NetCN1_20: CN1.20 J1.1 | length 4.6
  Top Layer w0.2: J1.1@5,9.77 5,13.13 CN1.20@5.87,14
NetCN2_1: CN2.1 U1.H4 | length 29.5
  Top Layer w0.09: U1.H4@31.5,-2.5 32.208,-2.5 33.171,-3.463 cw(c32.975,-3.848) 33.36,-3.652 35.269,-5.561 35.269,-6.562 36.227,-7.52 v1(36.227,-8.22)
  Bottom Layer w0.2: v1(36.227,-8.22) 38.673,-10.666 52.62,-10.666 cw(c52.62,-10.866) 52.762,-10.725 54.071,-12.034 cw(c53.93,-12.176) 54.13,-12.176 CN2.1@54.13,-14
NetCN2_2: CN2.2 U1.E5 | length 46.8
  MidLayer 1 w0.1: v1(20.578,-4.985) 22.082,-4.985 23.4,-3.667 27.333,-3.667 28.3,-2.7 29.3,-2.7 v2(30,-2)
  Bottom Layer w0.2: v1(20.578,-4.985) 20.578,-5.507 23.838,-8.768 30.042,-8.768 30.235,-8.96 36.011,-8.96 38.036,-10.986 50.459,-10.986 50.799,-11.326 cw(c50.658,-11.468) 50.8,-11.327 51.301,-11.828 cw(c51.16,-11.969) 51.36,-11.969 51.36,-13.77 CN2.2@51.59,-14
NetCN2_3: CN2.3 SB5.1 | length 7.3
  Top Layer w0.5: v2(49.738,-7.945) 50.461,-7.945 SB5.1@50.467,-7.952
  MidLayer 1 w0.3: CN2.3@49.05,-14 49.05,-8.263
  MidLayer 1 w0.4: 49.05,-8.263 v2(49.209,-8.104) 49.368,-7.945 v2(49.738,-7.945)
NetCN2_4: CN2.4 U1.J3 | length 23.5
  Top Layer w0.1: U1.J3@32,-3 32.5,-3.5 32.5,-3.738 ; 32.501,-3.739 32.501,-5.258 32.642,-5.399 32.642,-7.946 33.241,-8.545 33.672,-8.545 34.034,-8.545 34.098,-8.482 v2(34.828,-8.482)
  MidLayer 1 w0.1: v2(34.828,-8.482) 34.828,-9.481 36.03,-10.683 45.433,-10.683 46.51,-11.76 CN2.4@46.51,-14
NetCN2_7: CN2.7 U1.B9 | length 50.4
  Top Layer w0.1: v1(25.359,3.901) 25.359,3.044 26.501,1.901 26.501,1.77 28.011,0.26 28.24,0.26 U1.B9@28.5,0
  Bottom Layer w0.2: v1(25.359,3.901) 23.241,3.901 20.799,3.901 16.468,-0.43 16.468,-1.83 19.025,-4.387 19.025,-5.37 22.456,-8.801 22.456,-14.823 22.902,-15.27 38.137,-15.27 38.904,-14.503 38.88,-14.48 38.88,-14.09 38.89,-14.08 CN2.7@38.89,-14
NetCN2_12: CN2.12 U1.D6 | length 56.4
  Top Layer w0.1: v2(18.529,-0.906) v2(19.681,0.365)
  MidLayer 1 w0.1: v2(18.529,-0.906) 16.174,-0.906 4.066,-13.014 4.066,-14.12 5.016,-15.07 25.079,-15.07 ccw(c25.079,-14.97) 25.15,-15.04 CN2.12@26.19,-14 ; v2(19.681,0.365) 20.216,0.9 24.127,0.9 24.377,0.65 24.878,0.65 25.2,0.328 25.2,0.269 25.2,0.197 26.037,-0.64 26.109,-0.64 26.126,-0.64 26.961,-1.475 29.475,-1.475 v2(29.5,-1.5)
NetCN2_13: CN2.13 U1.F4 | length 20.8
  Top Layer w0.1: v2(32.975,-3.848) 34.323,-5.197 v2(34.323,-5.64)
  MidLayer 1 w0.1: CN2.13@23.65,-14 23.65,-12.7 26.05,-10.3 30.873,-10.3 34.223,-6.949 34.223,-5.74 ; v2(30.5,-2.5) 30.65,-2.65 31.776,-2.65 v2(32.975,-3.848)
NetCN2_14: CN2.14 U1.H3 | length 19.9
  Top Layer w0.09: CN2.14@21.163,-13.947 22.818,-12.292 23.157,-12.292 v2(23.157,-12.298)
  MidLayer 1 w0.1: v2(23.157,-12.298) 23.684,-12.298 25.955,-10.026 30.836,-10.026 33.074,-7.788 33.074,-4.574 v2(31.5,-3)
NetCN2_15: CN2.15 U1.H2 | length 21.6
  MidLayer 1 w0.1: CN2.15@18.57,-14 20.71,-11.86 23.726,-11.86 25.826,-9.76 30.786,-9.76 32.746,-7.799 32.746,-4.746 31.853,-3.853 v2(31.5,-3.5)
NetCN2_16: CN2.16 U1.G3 | length 24.4
  MidLayer 1 w0.1: CN2.16@16.03,-14 18.797,-11.233 23.933,-11.233 25.712,-9.454 30.78,-9.454 32.526,-7.708 32.526,-4.938 31,-3.412 v2(31,-3)
NetCN2_17: CN2.17 U1.D3 | length 23.2
  MidLayer 1 w0.1: CN2.17@13.49,-14 16.6,-10.89 22.476,-10.89 24.966,-8.4 28.55,-8.4 29.1,-7.85 29.1,-4 29.35,-3.75 29.35,-3.4 29.5,-3.25 v2(29.5,-3)
NetCN2_18: CN2.18 U1.C2 | length 24.8
  MidLayer 1 w0.1: CN2.18@10.95,-14 14.529,-10.421 22.563,-10.421 24.854,-8.13 28.45,-8.13 28.85,-7.73 28.85,-3.85 29,-3.7 v2(29,-3.5)
NetCN2_19: CN2.19 U1.J1 | length 34.2
  Top Layer w0.1: v2(16.253,-7.373) 17.006,-7.373 17.48,-7.846 26.788,-7.846 27.11,-8.168 29.369,-8.168 30.356,-7.181 31.057,-7.181 31.416,-6.822 31.416,-5.942 31.784,-5.574 31.784,-4.216 U1.J1@32,-4
  MidLayer 1 w0.1: CN2.19@8.41,-14 12.781,-9.629 17.474,-9.629 18.195,-8.908 18.195,-7.792 17.777,-7.373 v2(16.253,-7.373)
NetCN2_20: CN2.20 U1.J2 | length 32.7
  Top Layer w0.09: v2(16.828,-8.234) 16.977,-8.383 29.458,-8.383 30.367,-7.475 30.369,-7.475 30.447,-7.396 31.146,-7.396 31.631,-6.911 31.631,-6.212 32.316,-5.527 32.316,-3.816 U1.J2@32,-3.5
  MidLayer 1 w0.1: CN2.20@5.87,-14 11.646,-8.224 16.818,-8.224 v2(16.828,-8.234)
NetL2_2: L2.2 U1.B1 | length 3.9
  Top Layer w0.15: 28.5,-4.3 U1.B1@28.5,-4
  Top Layer w0.21: 28.5,-4.475 28.5,-4.3
  Top Layer w0.25: v1(28.25,-6.406) 28.375,-6.406 28.5,-6.281 28.5,-4.475
  Bottom Layer w0.8: v1(28.25,-6.406) 28.274,-6.43 28.274,-7.588 L2.2@28.354,-7.668
NetL6_2: L6.2 SB10.2
NetL11_2: L11.2 SB14.1 | length 1.9
  Top Layer w0.2: SB14.1@28.25,6.467 SB14.1@28.157,6.56 28.169,6.571 SB14.1@28.265,6.667 ; L11.2@29.238,6.319 L11.2@29.463,6.544
  Top Layer w0.3: SB14.1@28.157,6.571 28.169,6.571 L11.2@29.463,6.571
NetR1_2: R1.2 SB8.1 | length 1.4
  Top Layer w0.2: SB8.1@38.272,-7.578 39.606,-7.578 R1.2@39.637,-7.609
NetR2_2: R2.2 SB3.2 SB4.2 SB5.2 | length 4.1
  Top Layer w0.3: SB5.2@51.367,-7.952 51.407,-7.912 SB4.2@51.407,-5.152 ; SB4.2@51.367,-5.152 51.441,-5.078 R2.2@52.618,-5.078
NetR3_2: R3.2 SB6.2 SB9.2 | length 2.7
  Top Layer w0.3: SB9.2@50.05,7.195 SB6.2@50.05,5.794 50.056,5.789 R3.2@50.056,4.494
NetR6_1: R6.1 X3.3 | length 0.8
  Top Layer w0.12: R6.1@26.871,8.649 X3.3@27.599,8.649
  Top Layer w0.5: R6.1@26.866,8.654 R6.1@26.871,8.649 ; X3.3@27.599,8.649 27.649,8.599 X3.3@27.649,8.56
NetSB1_1: SB1.1 U1.B6 | length 5.2
  Top Layer w0.1: SB1.1@23.55,-1.669 23.577,-1.695 25.954,-1.695 26.104,-1.545 26.466,-1.545 26.616,-1.695 28.305,-1.695 U1.B6@28.5,-1.5
NetSB2_1: SB2.1 U1.C5 | length 6.4
  Top Layer w0.1: SB2.1@23.381,-2.7 24.1,-1.981 26.283,-1.981 v2(26.285,-1.983)
  MidLayer 1 w0.1: v2(26.285,-1.983) 27.229,-1.983 27.631,-2.385 28.847,-2.385 28.975,-2.256 28.975,-2.025 v2(29,-2)
NetSB4_1: SB4.1 U1.D5 | length 36.8
  Top Layer w0.5: v1(49.742,-5.197) 49.765,-5.175 50.406,-5.175 SB4.1@50.429,-5.152
  MidLayer 1 w0.1: v1(23.711,0.1) 23.927,0.317 24.77,0.317 25.946,-0.86 26.035,-0.86 26.87,-1.695 27.044,-1.695 27.048,-1.699 29.199,-1.699 v2(29.5,-2)
  Bottom Layer w0.2: v1(23.711,0.1) 23.927,0.317 25.88,0.317 26.097,0.1 27.9,0.1 32.247,-4.247 34.254,-6.254 48.685,-6.254 v1(49.742,-5.197)
NetSB6_1: SB6.1 U1.F3 | length 59.8
  Top Layer w0.3: v1@48.415,5.807 v1(48.427,5.794) SB6.1@49.15,5.794
  MidLayer 1 w0.1: v2(30.5,-3) 30.797,-3.297 30.797,-3.59 31.784,-4.576 31.784,-7.016 v1(30.515,-8.285)
  Bottom Layer w0.2: v1(30.515,-8.285) 31.528,-7.272 ; v1(48.427,5.794) 48.427,5.188 50.493,3.123 50.493,0.643 50.807,0.328 50.807,-6.402 50.413,-6.796 50.413,-6.82 50.018,-7.215 49.994,-7.215 49.937,-7.272 ; 31.528,-7.272 49.937,-7.272 ; 31.528,-7.272 49.937,-7.272
NetSB8_2: SB8.2 U1.J5 | length 8.3
  Top Layer w0.09: U1.J5@32,-2 32.3,-2 32.7,-2.4 32.7,-2.695 33.164,-3.159 33.244,-3.159 35.703,-5.618 35.703,-6.336 36.865,-7.499 37.293,-7.499 SB8.2@37.372,-7.578
NetSB10_1: SB10.1 U1.J8 | length 0.2
  Top Layer w0.17: U1.J8@32,-0.5 32.195,-0.5
NetSB10_3: SB10.3 U1.J9 | length 0.5
  Top Layer w0.15: U1.J9@32,0 32.5,0
OSC_IN: C38.2 U1.G9 | length 9.9
  Top Layer w0.12: C38.2@26.751,5.949 26.751,5.562 ccw(c27.129,5.562) 27.021,5.199 30.694,5.199 cw(c30.694,4.867) 31.026,4.867 31.026,0.026 U1.G9@31,0
PB0_VDD_TCXO: SB14.2 U1.F6 | length 10.5
  Top Layer w0.3: SB14.2@28.306,5.711 v2(29.991,5.711)
  Top Layer w0.4: SB14.2@28.121,5.659 28.14,5.677 SB14.2@28.157,5.66
  Top Layer w0.5: v2@29.991,5.704 v2@30.495,5.704
  MidLayer 1 w0.1: v2(30.5,-1.5) 30.844,-1.156 30.844,-0.85 30.722,-0.728
  MidLayer 1 w0.15: 30.722,-0.728 30.632,-0.638 30.632,-0.031 30.964,0.302
  MidLayer 1 w0.2: 30.541,5.491 31.017,5.015 31.017,1.576 31.081,1.512 31.081,1.504 31.089,1.504 31.089,0.427 30.964,0.302
  MidLayer 1 w0.5: v2@29.965,5.705 v2@30.541,5.705
  other v2: 30.522,5.711
RFI_N: C30.2 L8.2 U1.H7 | length 4.7
  Top Layer w0.1: U1.H7@31.5,-1 32.027,-1 32.316,-1.289 33.12,-1.289 33.472,-1.641 33.705,-1.641 34.104,-2.04 L8.2@34.586,-2.04 C30.2@35.771,-2.04
RFI_P: C36.1 L8.1 U1.J6 | length 4.6
  Top Layer w0.1: U1.J6@32,-1.5 33.033,-1.5 33.385,-1.852 33.618,-1.852 34.145,-2.38 34.145,-2.513 34.586,-2.954 L8.1@34.586,-3.2 C36.1@35.67,-3.2
VDD: C1.2 C2.2 C3.2 C4.2 C5.2 C35.1 C37.1 CN2.10 L1.1 SB11.2 U1.A7 U1.A8 U1.E2 U1.E9 U1.H5 | length 27.9
  Top Layer w0.15: 27.7,-1 U1.A7@28,-1 ; 27.7,-0.5 U1.A8@28,-0.5 ; U1.E9@30,0 30,0.3
  Top Layer w0.25: C4.2@28.559,2.384 29.016,2.384 29.258,2.142 29.258,1.115 29.46,0.913 29.46,0.899 30,0.359 30,0.3
  Top Layer w0.5: v1(27.593,2.397) v1@27.6,2.391
  Top Layer w0.55: 27.982,2.391 C4.2@28.553,2.391
  Top Layer w0.6: v1(24.579,2.628) 24.579,2.623 v1(25.328,1.874) 26.4,0.802 C3.2@26.4,-0.55 ; v3(30.609,-11.651) v3(30.609,-12.309) v3(31.6,-12.309) 31.6,-14 CN2.10@31.27,-14
  Top Layer w0.7: v1@27.595,2.389 27.982,2.389
  MidLayer 1 w0.1: v1@33.334,-2.502 v1(33.359,-2.477)
  MidLayer 1 w0.2: v2(31.5,-2) 31.926,-2 32.121,-2.195
  MidLayer 1 w0.25: v2(30,-3.5) 30.109,-3.609 30.109,-4.875 v1(30.409,-5.175)
  MidLayer 1 w0.3: 32.121,-2.195 32.428,-2.502 v1@33.334,-2.502
  Bottom Layer w0.25: C2.2@30,-5.9 C2.2@30.054,-5.846
  Bottom Layer w0.3: v1(18.5,-2.25) L1.1@19.9,-2.25
  Bottom Layer w0.5: C2.2@30.054,-5.846 30.054,-5.529 v1(30.409,-5.175)
  Bottom Layer w0.6: C37.1@29.726,-11.83 29.905,-11.651 v3(30.609,-11.651) v3@30.713,-11.755 ; v3(31.6,-12.309) 31.6,-11.516 32.611,-10.505 SB11.2@35.17,-10.505
  Bottom Layer w0.8: v1(24.579,2.628) v1@25.357,1.851 ; 25.328,2.446 27.545,2.446 v1(27.593,2.397)
VDDPA: C16.1 C31.1 C33.2 SB7.2 U1.H8 | length 2.7
  MidLayer 1 w0.4: v2(31.5,-0.5) 31.5,1.321 31.509,1.33 31.509,1.678 31.5,1.688 31.5,2.214 v2(31.505,2.219)
  other v2: 31.911,1.863 31.505,2.66 31.505,3.101 31.976,3.516 31.505,3.542 31.505,3.983 31.505,4.423 32.022,4.664 31.505,4.864 31.505,5.305 32.043,5.961 31.451,6.001
VDDRF: C10.1 C11.1 C24.1 C41.1 C110.1 CN2.8 SB3.1 SB7.3 SB11.1 U1.A2 U1.E8 | length 77
  Top Layer w0.15: 27.7,-3.5 U1.A2@28,-3.5
  Top Layer w0.25: C11.1@26.204,-4.552 27.256,-3.5 27.7,-3.5
  Top Layer w0.5: v1(49.738,-6.54) SB3.1@50.41,-6.54
  Top Layer w0.6: C11.1@25.816,-4.547 26.2,-4.547 C11.1@26.204,-4.552 ; SB7.3@31.756,7.588 31.756,8.188 ; 31.762,8.204 32.284,8.726 C110.1@32.659,8.726
  Top Layer w0.7: v1(23.744,-4.559) 24.687,-4.559 24.704,-4.542 25.811,-4.542 C11.1@25.816,-4.547 ; C41.1@29.885,2.15 29.885,1.478 v1@29.958,1.405 ; C110.1@32.659,8.726 v1@32.659,9.245 ; v1(32.67,9.531) 32.875,9.737 v1(34.041,9.737)
  MidLayer 1 w0.25: v1@29.958,1.405 30,1.363 v2(30,-0.5)
  MidLayer 2 w0.7: v1(32.67,9.531) 33.462,9.531 ; v1@33.835,9.531 v1(34.041,9.737)
  MidLayer 2 w1: 36.35,-11.866 37.001,-11.215 44.137,-11.215 48.812,-6.54 v1(49.738,-6.54)
  MidLayer 2 w1.1: 29,-4.247 29,-5.555 29.425,-5.98 29.425,-6.892
  MidLayer 2 w1.2: v1@23.524,-5.649 25.501,-7.626 28.691,-7.626 29.425,-6.892 ; v1@23.744,-4.601 24.341,-5.198 24.006,-5.533
  MidLayer 2 w1.5: 33.622,8.376 34.648,7.351 34.648,5.931 34.041,5.324
  MidLayer 2 w1.7: 29,-4.247 29,-3.367 30.458,-1.909 30.458,0.032 31.026,0.6 32.447,0.6 34.873,-1.827 34.873,-3.92 33.803,-4.991 33.803,-8.547 34.288,-9.033 34.288,-9.804 36.35,-11.866 CN2.8@36.35,-14 ; 33.962,5.111 34.041,5.19 34.041,5.324
  MidLayer 2 w2: 31.026,0.6 32.438,2.012 32.438,3.587 33.962,5.111
  Bottom Layer w0.6: SB11.1@36.339,-10.504 36.339,-11.8 36.369,-11.83 36.35,-11.849 CN2.8@36.35,-14
  other v1: 23.312,-5.533 30.008,1.405
VDDRF1V55: C14.1 C34.2 CN1.11 L2.1 SB7.1 U1.B2 U1.F7 | length 37.2
  Top Layer w0.25: v1@27.573,-5.287 v1(27.65,-5.21)
  Top Layer w0.4: C34.2@28.838,4.388 28.881,4.345 ccw(c29.089,4.553) 29.089,4.259 v1(29.769,4.259) v1@29.769,4.191
  MidLayer 1 w0.2: v1(29.769,4.259) 30.697,3.33 30.697,1.444 30.761,1.38 30.761,1.372 30.769,1.364 30.769,0.664 30.328,0.222 30.328,-0.636 30.296,-0.667 30.296,-0.796 v2(30.5,-1)
  MidLayer 1 w0.25: v1(27.65,-5.21) 27.65,-5.059 28.5,-4.209 v2(28.5,-3.5)
  MidLayer 2 w0.8: v1(27.65,-5.21) 27.65,-2.822 29.118,-1.354 29.118,0.917 29.033,1.002 29.033,1.808 29.604,2.38 29.682,2.38 29.769,2.466 v1(29.769,4.259) ; CN1.11@28.73,14 28.73,11.438 29.769,10.399 v1(29.769,4.259) ; v1(33.223,6.521) 30.96,4.259 v1(29.769,4.259)
  Bottom Layer w0.25: v1(27.65,-5.21) v1@27.656,-5.216
  Bottom Layer w0.6: L2.1@26.449,-7.668 26.629,-7.488 26.629,-6.584 26.95,-6.262 C14.1@26.95,-6.125 26.95,-5.987 27.64,-5.297 27.64,-5.22 v1(27.65,-5.21)
pads on no net: Designator1.1 U1.B4 U1.C4 U1.C6 U1.D4 U1.D7 U1.E4 U1.F2 U1.F8 U1.G2 U1.G4
copper on no net:
  other v2: 22.128,2.971 23.009,2.971 22.541,3.824

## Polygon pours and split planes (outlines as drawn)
VDD on MidLayer 2 "MIDLAYER_2_VDD_P026" (solid, remove dead copper, pour order 26): 30.079,-15.416 32.404,-15.416 32.739,-15.081 32.739,-4.938 33.262,-3.676 cw(c34.458,-4.171) 33.542,-3.256 ccw(c33.043,-2.757) 33.749,-2.757 33.749,-2.299 ccw(c33.551,-2.299) 33.551,-2.1 27.909,-2.1 27.909,2.441 ccw(c27.108,2.441) 27.286,3.222 26.652,3.365 ccw(c26.058,0.75) 25.031,3.228 20.758,1.458 ccw(c22.43,-2.58) 19.339,0.51 16.852,-1.977 ccw(c17.371,-2.495) 16.638,-2.495 16.638,-5.453 ccw(c17.345,-5.453) 16.845,-5.953 22.344,-11.452 ccw(c22.955,-10.841) 22.955,-11.705 27.995,-11.705 cw(c27.995,-12.972) 28.891,-12.076 29.455,-12.64 cw(c28.693,-13.402) 29.77,-13.402 29.77,-15.107
GND on MidLayer 2 "MIDLAYER_2_GND_P027" (solid, remove dead copper, pour order 27): 64.868,17.416 64.868,-17.511 0,-17.511 0,17.49
VDD on Bottom Layer "VDD_L-01_P-001" (solid, pour order 28): 29.351,-9.907 30.293,-9.907 32.667,-12.281 32.667,-13.385 32.667,-15.22 29.872,-15.22 29.872,-12.792 29.35,-12.269
GND on Bottom Layer "BOTTOM_LAYER_GND_P029" (solid, remove dead copper, pour order 29): -0.02,-17.435 -0.02,17.489 64.868,17.489 64.868,-17.511
GND on MidLayer 1 "MIDLAYER_1_GND_P025" (solid, remove dead copper, pour order 25): -0.02,-17.435 -0.02,17.489 64.868,17.489 64.868,-17.511
GND on Top Layer "TOP_LAYER_GND_P024" (solid, remove dead copper, pour order 24): 0,-17.435 0,17.489 64.868,17.489 64.868,-17.511

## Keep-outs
Keep-Out Layer:
  lines w1.2: -0.315,-18.109 65.472,-18.109 65.472,18.095 -0.315,18.095 -0.315,-18.109

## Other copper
Top Layer:
  rectangle net GND: 27.337,9.351 29.759,10.171
  region net VDD: 26.182,-0.202 27.203,-0.202 cw(c27.203,-0.905) 27.637,-0.352 cw(c27.535,-0.483) 27.7,-0.483 27.7,-1.049 cw(c27.646,-1.049) 27.646,-1.103 27.263,-1.103 cw(c27.263,-0.973) 27.172,-1.065 27.047,-0.94 ccw(c26.951,-1.035) 26.951,-0.9 26.182,-0.9
  region net VDDPA: 31.91,1.555 cw(c31.663,1.833) 31.291,1.834 31.291,2.934 31.291,3.836 31.291,4.171 31.291,5.13 31.291,6.075 31.522,6.306 31.98,6.306 32.237,6.049 32.237,2.195 cw(c31.433,2.203)
  region net NetC22_2: 48.054,-0.454 48.217,-0.452 cw(c49.114,-1.382) 49.18,-0.091 49.18,0.131 48.054,0.131
  region net GND: 28.232,3.005 27.777,3.005 27.711,3.071 27.711,3.606 27.967,3.862 28.744,3.862 cw(c28.744,3.701) 28.905,3.701 28.905,3.007
  region net NetL6_2: 34.693,-0.215 34.863,-0.215 35.18,-0.454 35.222,-0.454 35.222,0.128 35.18,0.128 34.864,0.367 34.693,0.367
  pour cut-out: 52.376,0.158 58.907,0.158 58.907,-0.724 52.368,-0.724
  pour cut-out: 43.122,0.277 46.12,0.277 46.12,-0.605 43.114,-0.605
  pour cut-out: 35.868,0.277 36.915,0.277 36.915,-0.605 35.86,-0.605
  pour cut-out: 19.72,-0.941 21.884,-0.941 21.884,-3.265 19.72,-3.265
  region net NetC28_1: 61.705,0.489 61.396,0.489 61.025,0.005 61.025,-0.562 61.393,-1.008 61.705,-1.008
  pour cut-out: 39.729,1.242 40.95,1.242 40.95,-0.605 39.712,-0.605
  pour cut-out: 32.5,-1.473 35.615,-1.473 36.421,-2.152 36.421,-5.675 34.664,-5.675 32.5,-3.511
  region net NetC25_1: 52.17,-0.576 51.433,-0.576 50.484,-0.491 50.485,-0.269 51.785,0.006 52.17,0.006
  region net NetSB10_3: 33.349,0.367 32.983,0.367 32.246,0.073 32.246,-0.073 32.829,-0.215 33.349,-0.215
  region net NetSB10_1: 34.143,-0.632 33.164,-0.632 32.319,-0.414 32.162,-0.415 32.162,-0.585 33.169,-0.94 33.912,-1.182 34.143,-1.182
  region net GND: 29.443,10.171 31.035,10.171 31.771,9.866 32.004,9.633 32.004,9.293 31.785,9.074 31.209,9.074 31.082,9.202 29.919,9.202 29.45,9.671
  region net GND: 32.588,2.487 32.588,3.29 32.678,3.394 32.678,4.414 32.947,4.414 32.947,5.835 35.375,5.835 35.375,3.572 34.206,3.487 33.276,2.487
  region net GND: 33.876,1.544 36.247,1.544 36.607,1.184 36.607,0.802 33.352,0.802 33.352,1.02
MidLayer 1:
  region net VDDPA: 31.281,6.24 32.125,6.24 32.265,6.101 32.265,3.011 cw(c25.634,3.335) 31.336,-0.065 31.336,5.095 31.131,5.638 31.131,6.09
  region net VDD: 33.22,-2.776 32.654,-2.521 32.654,-2.425 ccw(c31.826,0.758) 33.224,-2.219
  region net NetCN1_9: 18.534,-4.76 18.754,-5.34 18.686,-5.409 ccw(c17.021,-8.245) 18.137,-5.151
  region net VDDRF1V55: 27.489,-4.929 27.993,-4.566 28.077,-4.614 ccw(c31.247,-5.488) 27.97,-5.211
  pour cut-out: 41.53,1.684 41.53,0.647 48.676,0.647 48.676,-0.425 48.055,-1.047 39.067,-1.057 39.067,1.684
  pour cut-out: 51.657,0.595 61.189,0.595 61.621,1.082 64.868,1.082 64.868,-1.604 61.625,-1.604 61.19,-1.17 51.651,-1.17
MidLayer 2:
  region net VDDRF: 34.743,7.163 33.944,7.163 32.412,8.98 cw(c32.881,9.376) 32.267,9.376 32.267,9.754 cw(c32.672,9.754) 32.672,10.158 34.325,10.158 cw(c34.325,9.74) 34.743,9.74 34.743,7.782
  region net VDDRF: 36.44,-12.95 36.44,-10.718 35.523,-10.718
  region net VDDRF: 36.44,-12.95 36.44,-10.718 37.357,-10.718
  region net VDDRF1V55: 31.785,4.77 29.376,4.77 29.376,2.585
Bottom Layer:
  region net NetCN2_7: 25.341,4.223 25.383,3.583 25.321,3.582 cw(c25.318,4.135) 24.927,3.744 24.767,3.904 24.935,4.071 cw(c25.301,3.704) 25.301,4.223
  region net VDD: 32.855,-10.349 31.146,-11.784 30.556,-11.081
  region net VDD: 32.855,-10.349 31.146,-11.784 31.735,-12.486

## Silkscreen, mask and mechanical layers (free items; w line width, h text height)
Top Overlay:
  lines w0.1: 33.823,-1.354 33.823,-1.314 ; 35.876,-2.663 36.678,-2.663 37.142,-2.663
  text "UART_RX" at 2.2,11.55 h1.5 r270
  text "UART_TX" at 2.25,-5.6 h1.5 r270
  text "MB1842" at 6.995,-12.322 h2.5
Bottom Overlay:
  text "MB1842" at 16.504,-10.934 h2.5
Top Solder:
  lines w1.5: 55.203,1.326 55.203,9.519 ; 55.225,-7.823 55.225,-1.746 ; 55.228,-7.775 cw(c53.378,-7.775) 53.378,-9.625 16.478,-9.625 cw(c16.478,-7.775) 14.628,-7.775 14.628,9.725 cw(c16.478,9.725) 16.478,11.575 53.378,11.575 cw(c53.378,9.725) 55.228,9.725
M1-Board Shape:
  lines w0.3: 61.632,17.489 61.645,17.477 ; 0.296,-17.511 64.868,-17.511 64.868,17.489 0.296,17.489 0.296,-17.511
Drill Drawing:
  drawing of 330 lines, arcs and shapes, not listed
  text "Layer" at 0.896,150.603 h1.45
  text "Name" at 10.797,150.603 h1.45
  text "Material" at 33.219,150.603 h1.45
  text "Thickness" at 53.957,150.603 h1.45
  text "Constant" at 69.637,150.603 h1.45
  text "Board Layer Stack" at 83.39,150.603 h1.45
  text "Top Overlay" at 10.797,147.712 h1.45
  text "Top Solder" at 10.797,144.822 h1.45
  text "Solder Resist" at 33.219,144.822 h1.45
  text "2.01mil" at 53.957,144.822 h1.45
  text "3.7" at 69.637,144.822 h1.45
  text "1" at 0.896,141.931 h1.45
  text "Top Layer" at 10.797,141.931 h1.45
  text "1.38mil" at 53.957,141.931 h1.45
  text "Dielectric 1" at 10.797,139.04 h1.45
  text "1 x 2116" at 33.219,139.04 h1.45
  text "4.25mil" at 53.957,139.04 h1.45
  text "3.8" at 69.637,139.04 h1.45
  text "2" at 0.896,136.15 h1.45
  text "MidLayer 1" at 10.797,136.15 h1.45
  text "1.38mil" at 53.957,136.15 h1.45
  text "Dielectric 2" at 10.797,133.259 h1.45
  text "FR4" at 33.219,133.259 h1.45
  text "27.95mil" at 53.957,133.259 h1.45
  text "5" at 69.637,133.259 h1.45
  text "3" at 0.896,130.368 h1.45
  text "MidLayer 2" at 10.797,130.368 h1.45
  text "1.38mil" at 53.957,130.368 h1.45
  text "Dielectric 3" at 10.797,127.478 h1.45
  text "1 x 2116" at 33.219,127.478 h1.45
  text "4.25mil" at 53.957,127.478 h1.45
  text "3.8" at 69.637,127.478 h1.45
  text "4" at 0.896,124.587 h1.45
  text "Bottom Layer" at 10.797,124.587 h1.45
  text "1.38mil" at 53.957,124.587 h1.45
  text "Bottom Solder" at 10.797,121.696 h1.45
  text "Solder Resist" at 33.219,121.696 h1.45
  text "2.01mil" at 53.957,121.696 h1.45
  text "3.7" at 69.637,121.696 h1.45
  text "Bottom Overlay" at 10.797,118.806 h1.45
  text "Symbol" at 1.505,110.761 h1.77
  text "Count" at 13.956,110.761 h1.77
  text "Hole Size" at 28.704,110.761 h1.77
  text "Plated" at 55.481,110.761 h1.77
  text "Hole Type" at 67.932,110.761 h1.77
  text "Drill Layer Pair" at 85.979,110.761 h1.77
  text "Via/Pad" at 122.822,110.761 h1.77
  text "Pad Shape" at 137.335,110.761 h1.77
  text "Template" at 155.677,110.761 h1.77
  text "Description" at 171.663,110.761 h1.77
  text "Hole Tolerance (+)" at 192.657,110.761 h1.77
  text "Hole Tolerance (-)" at 225.435,110.761 h1.77
  text "Hole Length" at 258.213,110.761 h1.77
  text "Routed Path Length" at 279.501,110.761 h1.77
  text "44" at 13.956,107.077 h1.47
  text "39.37mil (1.000mm)" at 28.704,107.077 h1.47
  text "PTH" at 55.481,107.077 h1.47
  text "Round" at 67.932,107.077 h1.47
  text "Top Layer - Bottom Layer" at 85.979,107.077 h1.47
  text "Pad" at 122.822,107.077 h1.47
  text "(Mixed)" at 137.335,107.077 h1.47
  text "(Mixed)" at 155.677,107.077 h1.47
  text "-" at 258.213,107.077 h1.47
  text "-" at 279.501,107.077 h1.47
  text "890" at 13.956,103.394 h1.47
  text "7.87mil (0.200mm)" at 28.704,103.394 h1.47
  text "PTH" at 55.481,103.394 h1.47
  text "Round" at 67.932,103.394 h1.47
  text "Top Layer - Bottom Layer" at 85.979,103.394 h1.47
  text "Via" at 122.822,103.394 h1.47
  text "Rounded" at 137.335,103.394 h1.47
  text "(Mixed)" at 155.677,103.394 h1.47
  text "-" at 258.213,103.394 h1.47
  text "-" at 279.501,103.394 h1.47
  text "934 Total" at 13.956,99.71 h1.47
  text "mils" at 24.059,79.077 h2.54
  text "mils" at 35.112,79.077 h2.54

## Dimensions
0.296,17.489 to 0.296,-17.511 on M3-Top Dimensions
64.868,-17.511 to 0.296,-17.511 on M3-Top Dimensions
